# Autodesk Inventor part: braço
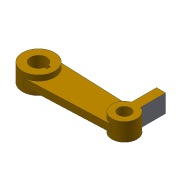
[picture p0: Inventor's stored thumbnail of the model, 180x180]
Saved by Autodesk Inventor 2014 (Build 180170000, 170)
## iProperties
Created: 2012-09
Part Number: braço
Material: Generic
Document SubType Name: Modelagem
Designer: TR-06
Density: 1 g/cm^3
Appearance: Default
Author: TR-06
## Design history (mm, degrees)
sketch "Sketch1"
  geometry: C1 r 56.25 at (0, 0); C2 r 43.75 at (300, 0); 1 further point
  constraints: 2 centre point, 1 coincident
  dimensions: "d0" = 112.5 diameter of C1; "d1" = 87.5 diameter of C2; "d2" = 300 distance of C2.centre C1.centre
extrude "Extrusion1" new body sketch "Sketch1" stored distance "d3" = 62.5; taper "d4" = 0 deg
sketch "Sketch2"
  geometry: L1 (0, 56.25)-(300, 43.75); L2 (300, -43.75)-(2.351, -56.201); A1 r 56.25 centre (0, 0) between (0, 56.25) and (2.351, -56.201) reference; A2 r 43.75 centre (300, 0) between (300, 43.75) and (300, -43.75) reference; 1 further point
  constraints: 4 end point, 4 point on circle, 1 tangent
extrude "Extrusion2" join sketch "Sketch2" stored distance "d5" = 25; taper "d6" = 0 deg
sketch "Sketch3"
  geometry: L1 (35.85, 6.3)-(27.436, 6.3); L2 (35.85, -6.3)-(27.436, -6.3); L3 (35.85, -6.3)-(35.85, 6.3); C1 r 56.25 at (0, 0) reference; A1 r 28.15 centre (0, 0) between (27.436, 6.3) and (27.436, -6.3)
  constraints: 6 end point, 2 point on circle, 1 centre point, 1 coincident, 1 perpendicular
  dimensions: "d7" = 56.3 diameter of A1; "d11" = 35.85 distance from line of L3 C1.centre; "d12" = 12.6 distance of L2.start L1.start
extrude "Extrusion3" cut sketch "Sketch3" stored distance "d13" = 25; taper "d14" = 0 deg
sketch "Sketch4"
  geometry: C1 r 43.75 at (0, 0) reference; C2 r 21.9 at (0, 0); 1 further point
  constraints: 1 centre point, 1 coincident
  dimensions: "d15" = 43.8 diameter of C2
extrude "Extrusion4" cut sketch "Sketch4" stored distance "d16" = 25; taper "d17" = 0 deg
body "Solid1"
node "Projected Loop1"
other parameters: "Espessura" = 0.5, "FatorK" = 4.4, "Raio_dobra" = 0.5 (= Espessura), "Largura_alívio_de_dobra" = 0.5 (= Espessura), "Profundidade_alívio_de_dobra" = 0.25 (= 0.5 x Espessura), "Tamanho_alívio_de_dobra" = 2 (= 4 x Espessura), "Folga_entre_junção" = 0.01, "Remanescente_mínimo" = 1 (= 2 x Espessura), "Raiodetransição" = 0.5 (= Raio_dobra), "Tamanho_de_raio_de_Jacobi" = 0.5 (= Espessura), "TamanhoFolga" = 0.5 (= Espessura)
